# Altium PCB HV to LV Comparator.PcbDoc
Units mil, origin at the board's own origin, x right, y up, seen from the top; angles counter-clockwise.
Board outline 2000 x 2000 mil, 2 copper layers (Top Layer, Bottom Layer), stack 62 mil thick; 42 components, 18 nets, 76 pads, 8 vias.
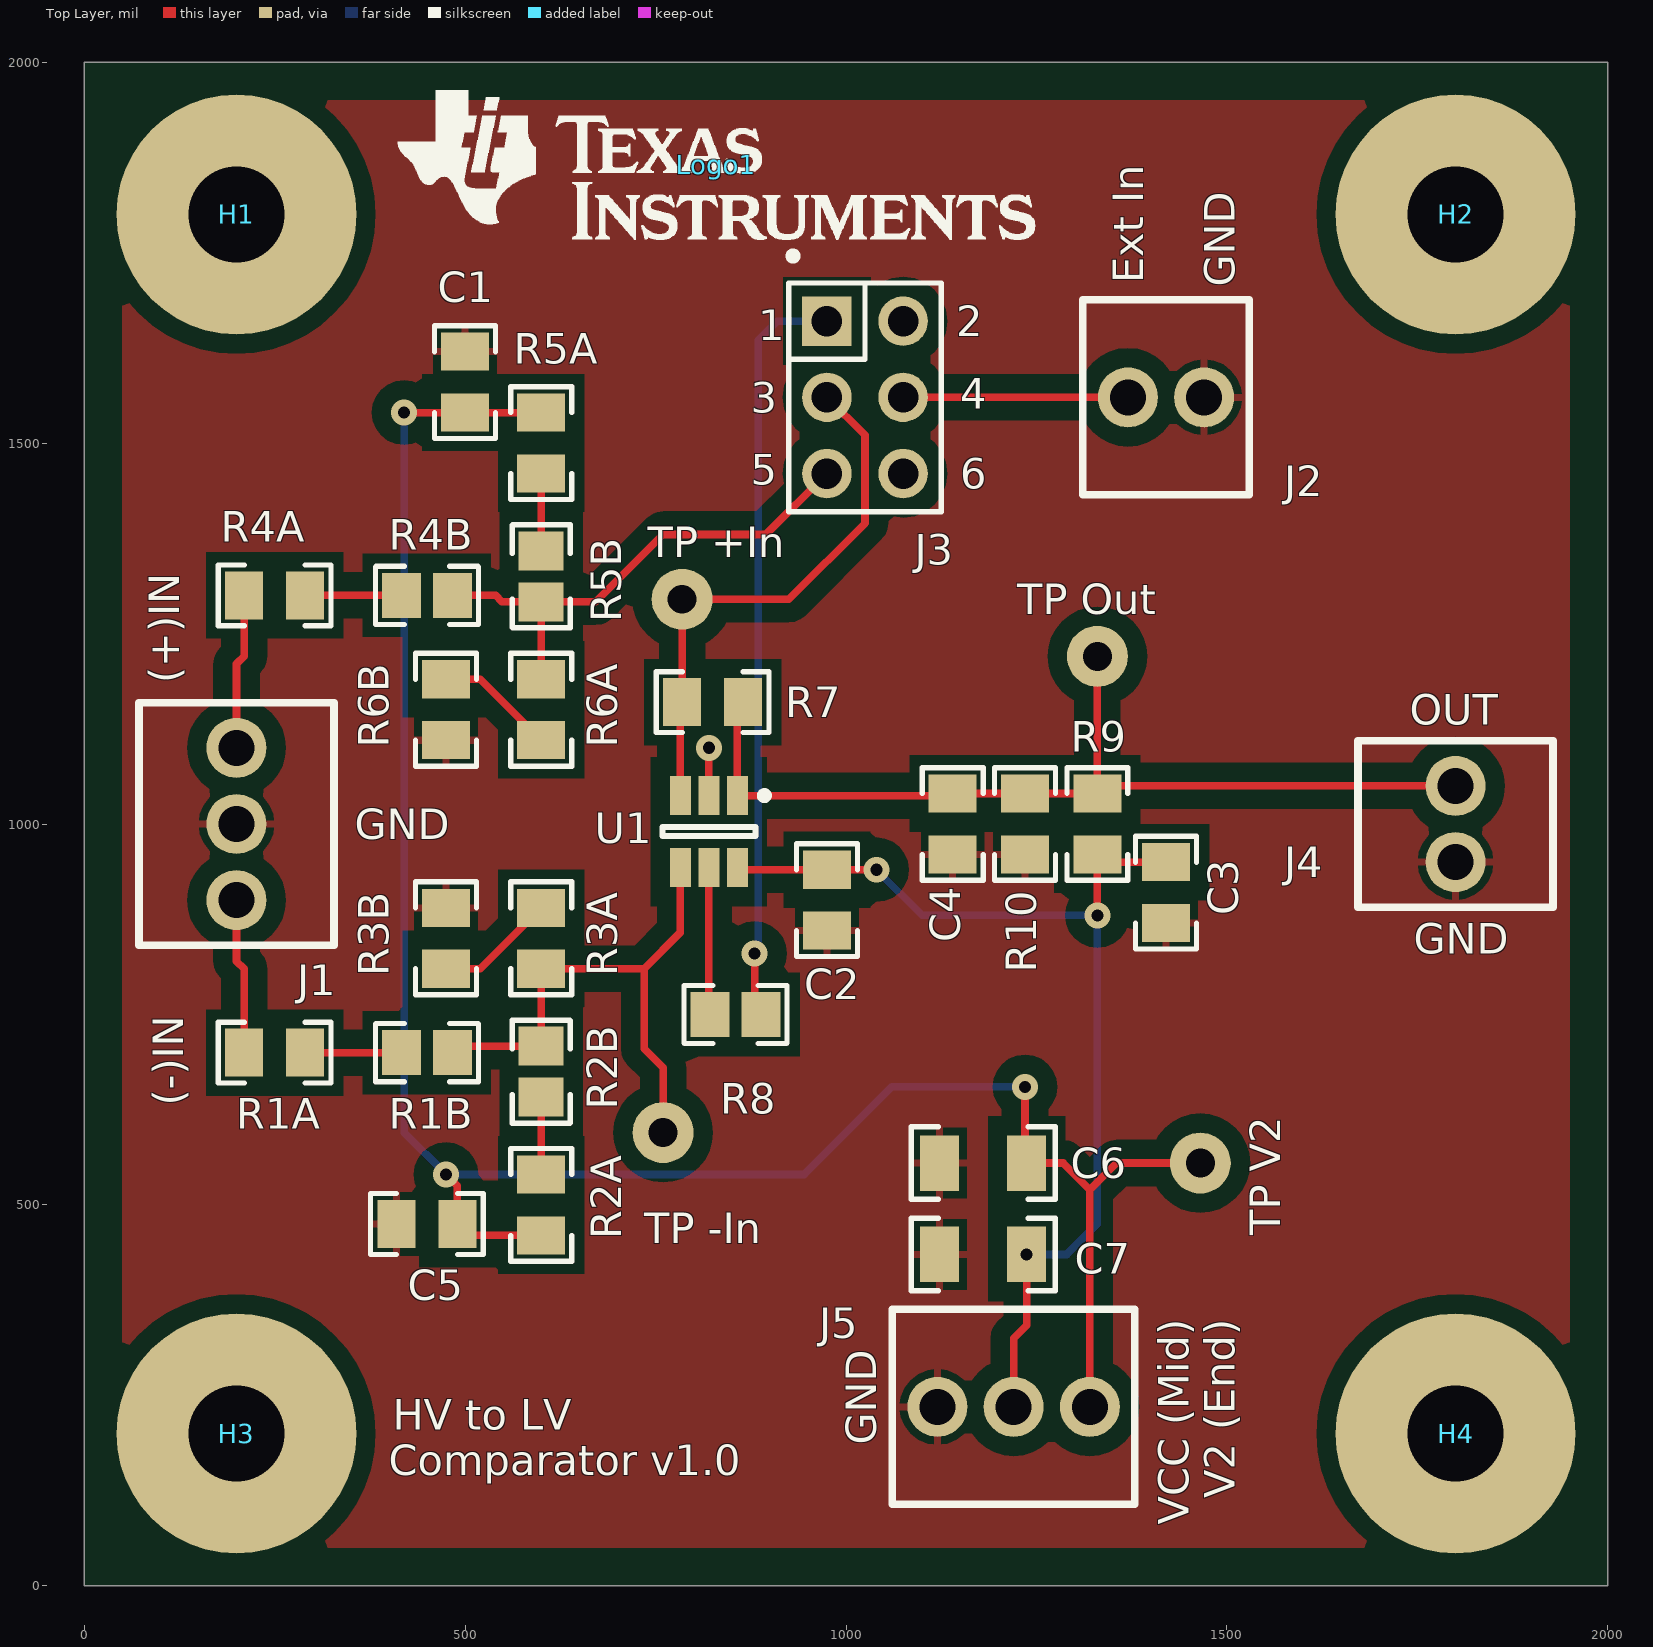
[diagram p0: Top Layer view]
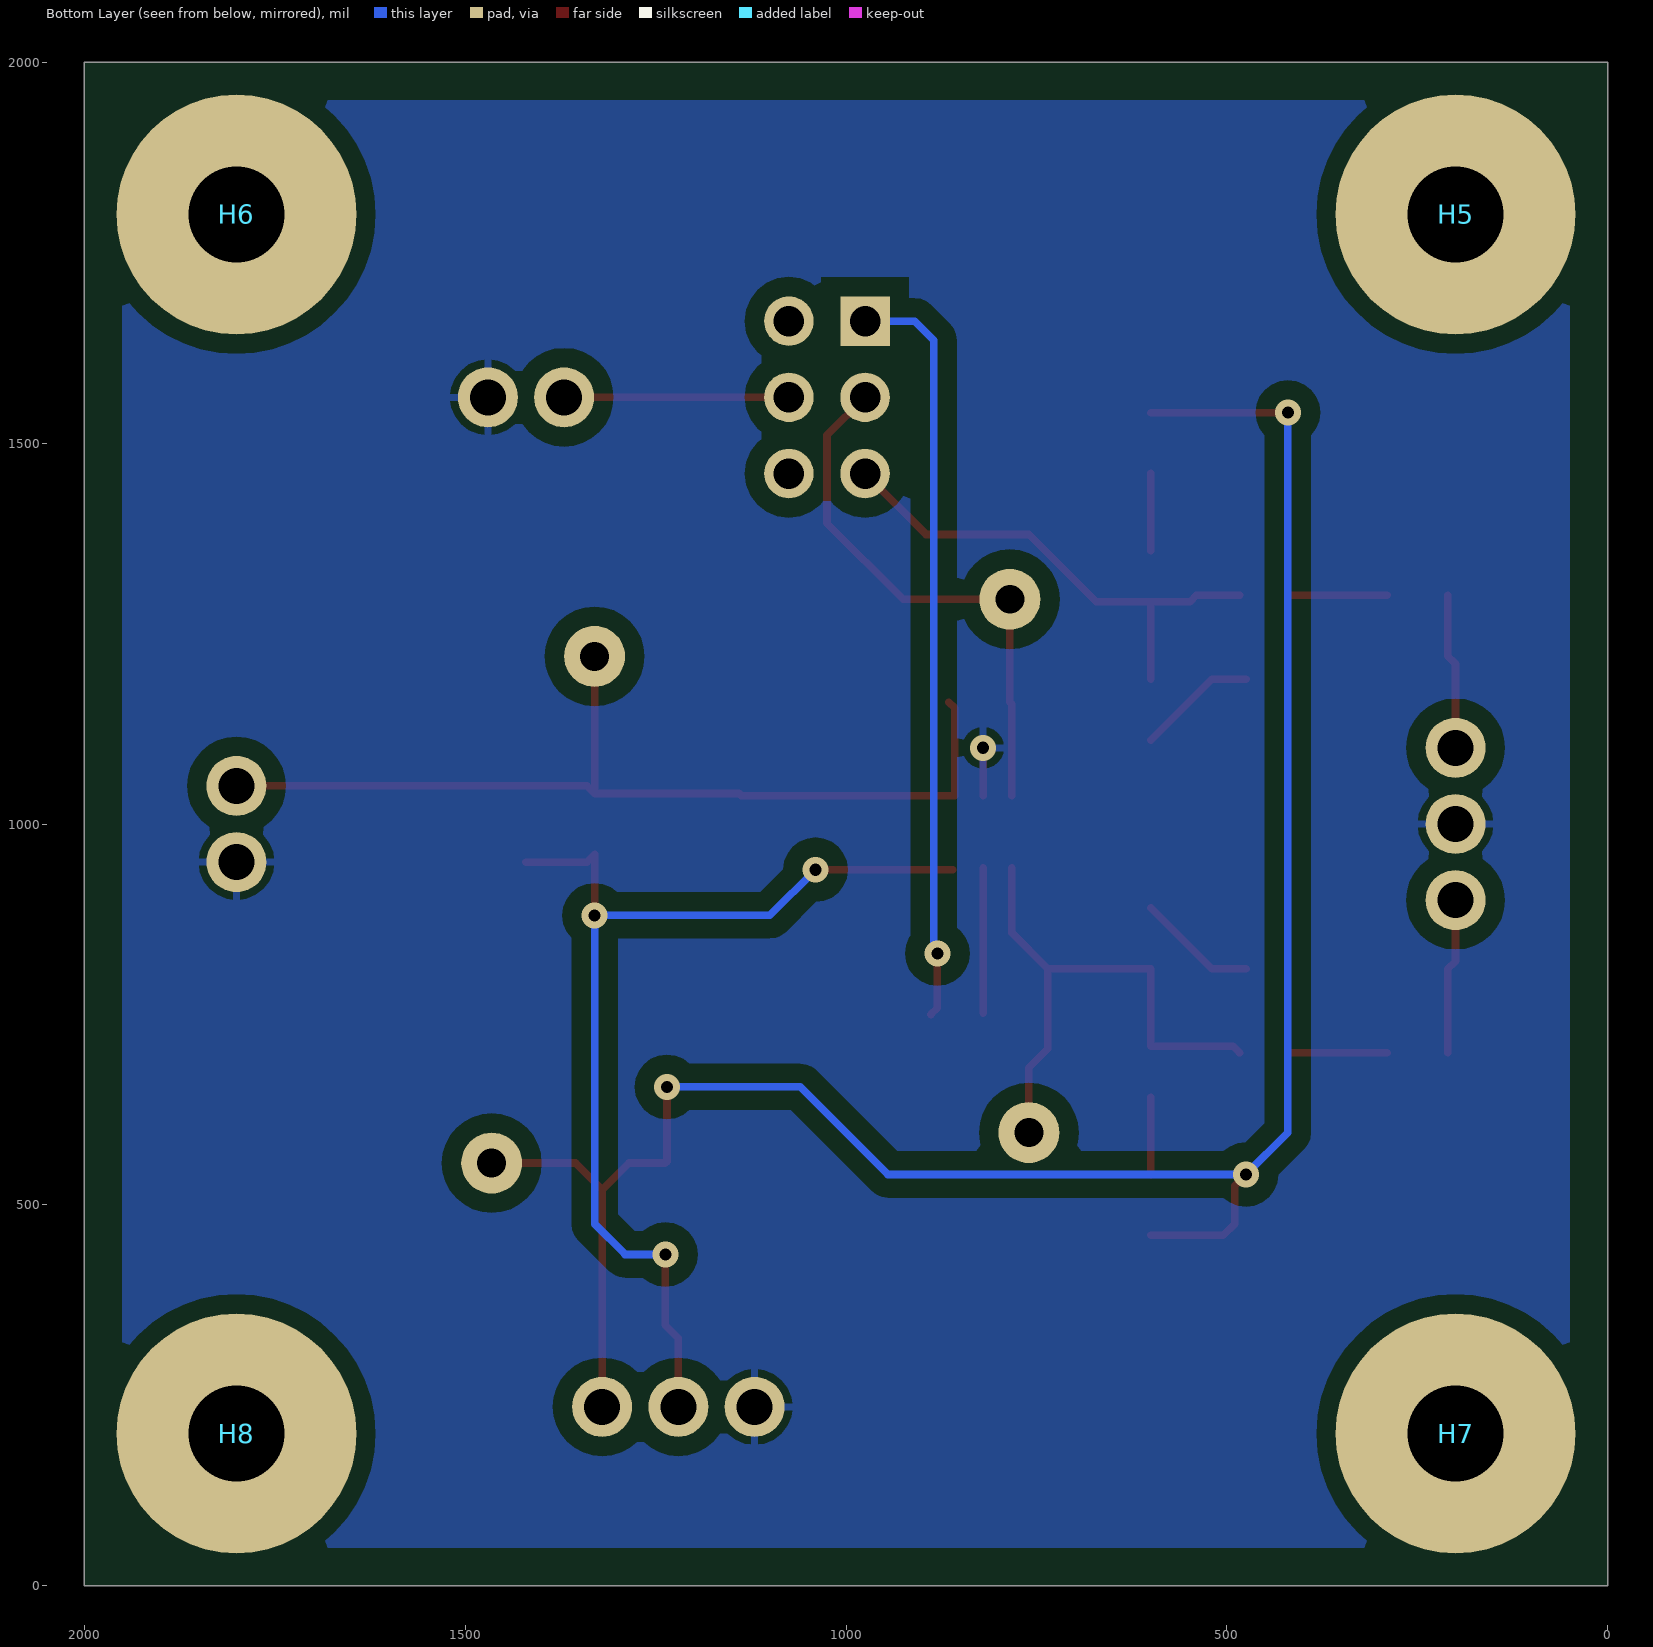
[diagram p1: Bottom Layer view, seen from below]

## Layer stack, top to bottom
Top Layer: signal copper 1.4
Dielectric: core 59.2, FR-4, Dk 4.8
Bottom Layer: signal copper 1.4

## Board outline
0,0 2000,0 2000,2000 0,2000

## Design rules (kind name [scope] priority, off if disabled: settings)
AcuteAngle [All] p1: minimum=4.50000000000000E+0001 checktracksonly=FALSE
AssemblyTestPointUsage [All] p1: valid=2
Clearance Clearance_BoardEdge_MountingHoles [OnCopper and InComponentClass('Mounting Holes') vs IsKeepOut] p1: gap=40
Clearance Clearance_BoardEdge_Poly [OnCopper and InPoly vs IsKeepOut] p2: gap=25
Clearance Clearance_BoardEdge [OnCopper and Not InComponentClass('Logo') and not InComponentClass('FiducialMark') and not InRegion(1000,500,4000,800) and Not IsKeepout vs IsKeepOut] p3: gap=75
Clearance Clearance_Poly [InPolygon] p4: gap=25
Clearance [All] p5: gap=8
ComponentClearance ComponentClearance_Logo [InComponentClass('Logo')] p1: gap=10 collisioncheckmode=3 verticalgap=10 showdistances=FALSE
ComponentClearance ComponentClearance_ScrewToNut [(HasFootprint('NY PMS 440 0025 PH')) vs (HasFootprint('Keystone_1902C'))] p2: gap=5 collisioncheckmode=3 verticalgap=10 showdistances=FALSE
ComponentClearance ComponentClearance_MountingHoles [InComponentClass('Mounting Holes')] p3: gap=50 collisioncheckmode=3 verticalgap=100000 showdistances=FALSE
ComponentClearance ComponentClearance_SmallPassives [HasFootprint('0201*') or HasFootprint('0402*') or HasFootprint('0508') or HasFootprint('0603*') or HasFootprint('0612') or HasFootprint('0805*') or HasFootprint('0815*') or HasFootprint('0830*') or HasFootprint('1206*') or HasFootprint('1210*') or HasFootprint('1808*') or HasFootprint('1812*') or HasFootprint('1825*') or HasFootprint('2010*') or HasFootprint('2220*') or HasFootprint('2225*') or HasFootprint('2512*') or HasFootprint('2728*') or HasFootprint('3518*') vs HasFootprint('0201*') or HasFootprint('0402*') or HasFootprint('0508') or HasFootprint('0603*') or HasFootprint('0612') or HasFootprint('0805*') or HasFootprint('0815*') or HasFootprint('0830*') or HasFootprint('1206*') or HasFootprint('1210*') or HasFootprint('1808*') or HasFootprint('1812*') or HasFootprint('1825*') or HasFootprint('2010*') or HasFootprint('2220*') or HasFootprint('2225*') or HasFootprint('2512*') or HasFootprint('2728*') or HasFootprint('3518*')] p4: gap=20 collisioncheckmode=3 verticalgap=10 showdistances=FALSE
ComponentClearance ComponentClearance_THtoSMT [IsThruComponent vs IsSMTComponent] p5: gap=20 collisioncheckmode=3 verticalgap=10 showdistances=FALSE
ComponentClearance ComponentClearance_THtoTH [IsThruComponent vs IsThruComponent] p6: gap=118.11 collisioncheckmode=3 verticalgap=30 showdistances=FALSE
ComponentClearance [All] p7: gap=40 collisioncheckmode=3 verticalgap=10 showdistances=FALSE
DiffPairsRouting [All] p1: maxlimit=100 minlimit=10 mostfreqgap=10 maxuncoupledlength=1000
FabricationTestPointUsage TestPointUsage [All] p1: valid=2 allowmultiple=FALSE
FabricationTestpoint Testpoint [All] p1: side=3 testpointundercomponent=TRUE minsize=40 maxsize=100 preferedsize=60 minholesize=0 maxholesize=40 preferedholesize=32 testpointgrid=1 allowsidetop=TRUE allowsidebottom=TRUE usegrid=TRUE gridtolerance=0.01
FanoutControl Fanout_LCC [IsLCC] p1: bgadir=Out bgaviamode=Centered fanoutstyle=Auto fanoutdirection=Alternating viagrid=1 // Fanout_LCC (Default Rule)
FanoutControl Fanout_BGA [IsBGA] p2: bgadir=Out bgaviamode=Centered fanoutstyle=Auto fanoutdirection=Alternating viagrid=1 // Fanout_BGA (Default Rule)
FanoutControl Fanout_Default [All] p4: bgadir=Out bgaviamode=Centered fanoutstyle=Auto fanoutdirection=Alternating viagrid=1 // Fanout_Default (Default Rule)
FanoutControl Fanout_Small [(CompPinCount < 5)] p5: bgadir=Out bgaviamode=Centered fanoutstyle=Auto fanoutdirection=OutThenIn viagrid=1 // Fanout_Small (Default Rule)
HoleSize [All] p1: absolutevalues=TRUE maxlimit=251 minlimit=8 maxpercent=80.000 minpercent=20.000
MinimumAnnularRing [All] p1: minimumring=9
MinimumSolderMaskSliver MinimumSolderMaskSliver_Logo [InComponentClass('Logo') vs InComponentClass('Logo')] p1: minsoldermaskwidth=0.7
MinimumSolderMaskSliver [All] p2: minsoldermaskwidth=4
PlaneConnect [All] p1: planeconnectstyle=Relief reliefexpansion=10 reliefentries=4 reliefconductorwidth=10 reliefairgap=10
PolygonConnect [All] p1: connectstyle=Relief reliefconductorwidth=10 reliefentries=4 polygonreliefangle="90 Angle" airgapwidth=10
RoutingVias [All] p1: holewidth=16 width=34 viastyle="Through Hole" minholewidth=8 minwidth=26 maxholewidth=40 maxwidth=65
SMDToCorner [All] p1: distance=30000
SilkToSilkClearance [All] p1: silktosilkclearance=5
SilkscreenOverComponentPads [All] p1: minsilkscreentomaskgap=5
SolderMaskExpansion [All] p1: expansion=3
Width [All] p1: maxlimit=100 minlimit=6 preferedwidth=10 checkconnectedcopper=TRUE
14 further rules are at their usual default settings.

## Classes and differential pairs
component class "Mounting Holes": H1 H2 H3 H4
component class Logo: Logo1
component class Hardware_ANSI-B: H1 H2 H3 H4 H5 H6 H7 H8 Logo1
component class Header: J3
component class HV_LV_Schematic: C1 C2 C3 C4 C5 C6 C7 J1 J2 J3 J4 J5 R1A R1B R2A R2B R3A R3B R4A R4B R5A R5B R6A R6B R7 R8 R9 R10 "TP +In" "TP -In" "TP Out" "TP V2" U1

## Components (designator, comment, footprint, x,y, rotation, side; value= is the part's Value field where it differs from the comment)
C1 "C2012X7R2A103K" 0805_HV 500,1580 r270 top
C2 "C2012X7R2A103K" 0805_HV 975,900 r90 top
C3 "C2012X7R2A103K" 0805_HV 1420,910 r90 top
C4 "C0805C100J1GACTU" 0805_HV 1140,1000 r270 top
C5 "C2012X7R2A103K" 0805_HV 450,475 r180 top
C6 "12063C105KAT2A" 1206 1180,555 r180 top
C7 "12063C105KAT2A" 1206 1180,435 r180 top
H1 "NY PMS 440 0025 PH" "NY PMS 440 0025 PH" 200,1800 r0 top locked
H2 "NY PMS 440 0025 PH" "NY PMS 440 0025 PH" 1800,1800 r0 top locked
H3 "NY PMS 440 0025 PH" "NY PMS 440 0025 PH" 200,200 r0 top locked
H4 "NY PMS 440 0025 PH" "NY PMS 440 0025 PH" 1800,200 r0 top locked
H5 "1902C" Keystone_1902C 200,1800 r180 bottom locked
H6 "1902C" Keystone_1902C 1800,1800 r180 bottom locked
H7 "1902C" Keystone_1902C 200,200 r180 bottom locked
H8 "1902C" Keystone_1902C 1800,200 r180 bottom locked
J1 "282834-3" "3 Contact Terminal Block" 200,900 r90 top
J2 "282834-2" "2 Contact Terminal Block" 1470,1560 r180 top
J3 "TSW-103-07-G-D" TSW-103-07-G-D 1025,1560 r270 top
J4 "282834-2" "2 Contact Terminal Block" 1800,950 r90 top
J5 "282834-3" "3 Contact Terminal Block" 1120,235 r0 top
Logo1 "Texas Instruments" TI_Stacked_Overlay_Small 830,1865 r0 top
R1A "RT0805BRD07232KL" 0805_HV 250,700 r0 top
R1B "Used in BOM report" 0805 450,700 r0 top
R2A "RT0805BRD0749K9L" 0805_HV 600,500 r270 top
R2B "Used in BOM report" 0805 600,675 r270 top
R3A "RT0805BRD0734K4L" 0805_HV 600,850 r270 top
R3B "RT0805BRD07100RL" 0805_HV 475,850 r270 top
R4A "RT0805BRD07232KL" 0805_HV 250,1300 r0 top
R4B "Used in BOM report" 0805 450,1300 r0 top
R5A "RT0805BRD0749K9L" 0805_HV 600,1500 r90 top
R5B "Used in BOM report" 0805 600,1325 r90 top
R6A "RT0805BRD0734K4L" 0805_HV 600,1150 r90 top
R6B "RT0805BRD07100RL" 0805_HV 475,1150 r90 top
R7 "CRCW08051M00FKEA" 0805_HV 825,1160 r0 top
R8 "Used in BOM report" 0805 855,750 r180 top
R9 "CRCW0805100KJNEA" 0805_HV 1330,1000 r270 top
R10 "CRCW0805100KJNEA" 0805_HV 1235,1000 r90 top
"TP +In" "TESTPOINT" TESTPOINT 785,1295 r90 top
"TP -In" "TESTPOINT" TESTPOINT 760,595 r90 top
"TP Out" "TESTPOINT" TESTPOINT 1330,1220 r90 top
"TP V2" "TESTPOINT" TESTPOINT 1465,555 r180 top
U1 "TLV3011AIDBVR" DBV0006A_M 820,990 r270 top

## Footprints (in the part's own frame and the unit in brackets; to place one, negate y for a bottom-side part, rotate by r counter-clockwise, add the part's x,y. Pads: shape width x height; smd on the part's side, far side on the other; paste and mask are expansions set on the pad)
"2 Contact Terminal Block" [mm]
  round 2 hole 1.2: 1(0,0) 2(2.54,0)
  silkscreen extent -1.5,-3.25 4.04,3.25
"3 Contact Terminal Block" [mm]
  round 2 hole 1.2: 1(0,0) 2(2.54,0) 3(5.08,0)
  silkscreen extent -1.5,-3.25 6.58,3.25
0805 [mm] "0805 from SM-752 data"
  rect 1.3x1.5 smd: 1(-0.85,0) 2(0.85,0)
  silkscreen extent -1.72,-0.97 1.72,0.97, body extent -1.1,-0.72 1.1,0.72, height 1.1
0805_HV [mil] "0805 with 30mil clearance between pads"
  rect 50x63 smd: 1(-40,0) 2(40,0)
  silkscreen extent -74,-40 74,40, body extent -43,-29 43,29, height 43
1206 [mm] "1206 from SM-752 data"
  rect 1.3x1.85 smd: 1(-1.45,0) 2(1.45,0)
  silkscreen extent -2.4,-1.21 2.4,1.21, body extent -1.7,-0.9 1.7,0.9, height 1.35
DBV0006A_M [mm] "SOT23, 6-Leads, Body 2.9x1.6mm, Pitch 0.95mm, Lead Span 2.8mm, IPC Low Density"
  rect 1.3x0.7 smd: 1(-1.2,0.95) 2(-1.2,0) 3(-1.2,-0.95) 4(1.2,-0.95) 5(1.2,0) 6(1.2,0.95)
  silkscreen extent -1.32,-1.55 0.15,1.98, body extent -0.87,-1.52 0.87,1.53, height 1.45
Keystone_1902C [mil] "Hex Standoff, 4-40 threaded, nylon"
  body extent -145,-126 146,126, height 501
"NY PMS 440 0025 PH" [mm] "4-40 nylon screw and mounting hole"
  round 8 hole 3.2: 1(0,0)
  body extent -3.3,-3.3 3.3,3.3, height 2.69
TESTPOINT [mil]
  round 80 hole 37.99: 1(0,0)
TI_Stacked_Overlay_Small [mil]
  silkscreen extent -418,-98 418,98
TSW-103-07-G-D [mm] "Samtec 100mil, 2x3, 230 mil above insulator"
  rect 1.65x1.65 hole 1.016 mask+0: 1(-2.54,-1.27)
  round 1.65 hole 1.016 mask+0: 2(-2.54,1.27) 3(0,-1.27) 4(0,1.27) 5(2.54,-1.27) 6(2.54,1.27)
  silkscreen extent -4.83,-2.54 3.81,2.54, body extent -3.81,-2.54 3.81,2.54, height 8.38

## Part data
C1 C2 C3 C5: "CAP, CERM, 0.01uF, 100V, +/-10%, X7R, 0805"
C4: "CAP, CERM, 10pF, 100V, +/-5%, C0G/NP0, 0805"
C6 C7: "CAP, CERM, 1uF, 25V, +/-10%, X7R, 1206"
H1 H2 H3 H4: "Machine Screw, Round, #4-40 x 1/4, Nylon, Philips panhead"
H5 H6 H7 H8: "Standoff, Hex, 0.5\"L #4-40 Nylon"
J1 J5: library part "TERM BLOCK 3POS SIDE ENT", "3 contact eurostyle terminal block"
J2 J4: library part "TERM BLOCK 2POS SIDE ENT", "2 contact eurostyle terminal block"
J3: "Header, TH, 100mil, 3x2, Gold plated, 230 mil above insulator"
Logo1: library part TI_Logo, "Texas Instrument Corporate Signature"
R1A R4A: "RES, 232k ohm, 0.1%, 0.125W, 0805"
R1B R2B R4B R5B R8: library part Resistor, "RES 0.0 OHM 1/8W JUMP 0805 SMD"
R2A R5A: "RES, 49.9k ohm, 0.1%, 0.125W, 0805"
R3A R6A: "RES, 34.4k ohm, 0.1%, 0.125W, 0805"
R3B R6B: "RES, 100 ohm, 0.1%, 0.125W, 0805"
R7: "RES, 1.00Meg ohm, 1%, 0.125W, 0805"
R9 R10: "RES, 100k ohm, 5%, 0.125W, 0805"
"TP +In" "TP -In" "TP Out" "TP V2": "TEST POINT.  No entry in BOM."
U1: "Nanopower, 1.8V, SOT23 Comparator with Voltage Reference"

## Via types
v1: diameter 34, hole 16, Top Layer to Bottom Layer, 8 vias

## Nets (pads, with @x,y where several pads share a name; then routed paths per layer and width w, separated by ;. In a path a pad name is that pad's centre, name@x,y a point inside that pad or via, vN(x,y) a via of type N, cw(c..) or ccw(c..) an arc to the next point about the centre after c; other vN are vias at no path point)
GND: C1.1 C2.1 C3.1 C4.2 C5.2 C6.2 C7.2 J1.2 J2.1 J4.1 J5.1 R3B.1 R6B.1 R10.1 U1.2 | length 62.8
  Top Layer w10: U1.2 v1(820,1100)
NetC4_1: "TP Out.1" C4.1 J4.2 R7.2 R9.1 R10.2 U1.1 | length 1253.8
  Top Layer w10: R7.2 857.4,1152.4 U1.1 1137.24,1037.24 C4.1 R10.2 R9.1 ; 1330,1220 R9.1 ; J4.2 1340,1050 R9.1
NetJ1_1: J1.1 R1A.1 | length 204.1
  Top Layer w10: J1.1 200,820 210,810 R1A.1
NetJ1_3: J1.3 R4A.1 | length 204.1
  Top Layer w10: J1.3 200,1210 210,1220 R4A.1
NetJ2_2: J2.2 J3.4 | length 295
  Top Layer w10: J3.4 J2.2
NetJ3_1: J3.1 R8.1 | length 993.9
  Top Layer w10: v1(880,830) 880,758.46 R8.1
  Bottom Layer w10: v1(880,830) 885,830 885,1635 910,1660 J3.1
NetJ3_3: "TP +In.1" J3.3 R7.1 U1.3 | length 722.5
  Top Layer w10: U1.3 R7.1@782.6,1157.6 ; R7.1 785,1295 925,1295 1025,1395 1025,1510 J3.3
NetJ3_5: J3.5 R4B.2 R5B.1 R6A.2 | length 666.4
  Top Layer w10: R4B.2 540,1300 548.46,1291.54 R5B.1 ; R6A.2 R5B.1 ; J3.5 895,1380 760,1380 671.54,1291.54 R5B.1
NetR1A_2: R1A.2 R1B.1 | length 126.5
  Top Layer w10: R1A.2 R1B.1
NetR1B_2: "TP -In.1" R1B.2 R2B.1 R3A.2 U1.4 | length 734.4
  Top Layer w10: R1B.2 491.93,708.46 R2B.1 R3A.2 735,810 ; 760,595 760,680 735,705 735,810 ; U1.4 782.6,857.6 735,810
NetR2A_1: R2A.1 R2B.2 | length 101.5
  Top Layer w10: R2A.1 R2B.2
NetR3A_1: R3A.1 R3B.2 | length 158.1
  Top Layer w10: R3B.2 520,810 R3A.1
NetR4A_2: R4A.2 R4B.1 | length 126.5
  Top Layer w10: R4A.2 R4B.1
NetR5A_1: R5A.1 R5B.2 | length 101.5
  Top Layer w10: R5B.2 R5A.1
NetR6A_1: R6A.1 R6B.2 | length 158.1
  Top Layer w10: R6B.2 520,1190 R6A.1
NetR8_2: R8.2 U1.5 | length 191.2
  Top Layer w10: R8.2@820,751.54 U1.5
V2: "TP V2.1" C1.2 C5.1 C6.1 J5.3 R2A.2 R5A.2 | length 2837.7
  Top Layer w10: v1(420,1540) C1.2 R5A.2 ; v1(475,540) 490,525 C5.1 505,460 R2A.2 ; C6.1@1235,557.09 v1(1235,655) ; C6.1 1285,555 1320,520 ; J5.3 1320,520 ; 1465,555 1355,555 1320,520
  Bottom Layer w10: v1(420,1540) 420,595 v1(475,540) 945,540 1060,655 v1(1235,655)
VCC: C2.2 C3.2 C7.1 J5.2 R9.2 U1.6 | length 1390.4
  Top Layer w10: U1.6@860.16,940 C2.2 v1(1040,940) ; J5.2 1220,325 1237.09,342.09 v1(1237.09,435) ; v1(1330,880) R9.2 1340,950 C3.2
  Bottom Layer w10: v1(1040,940) 1100,880 v1(1330,880) 1330,475 1290,435 v1(1237.09,435)
pads on no net: H1.1 H2.1 H3.1 H4.1 J3.2 J3.6

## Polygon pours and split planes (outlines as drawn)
GND on Bottom Layer "Bottom Layer-GND" (solid, remove dead copper, pour order 4): 50,1950 50,50 1950,50 1950,1950
GND on Top Layer "Top Layer-GND" (solid, remove dead copper, pour order 2): 50,50 1950,50 1950,1950 50,1950

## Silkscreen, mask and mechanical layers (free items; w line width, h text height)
Top Overlay:
  text "Ext In" at 1390,1710 h40 r90
  text "GND" at 1510,1705 h40 r90
  text "2" at 1145,1640 h40
  text "1" at 885,1635 h40
  text "4" at 1150,1545 h40
  text "3" at 875,1540 h40
  text "5" at 875,1445 h40
  text "6" at 1150,1440 h40
  text "(+)IN" at 125,1185 h40 r90
  text "OUT" at 1740,1130 h40
  text "GND" at 355,980 h40
  text "GND" at 1745,830 h40
  text "(-)IN" at 130,630 h40 r90
  text "HV to LV" at 405,205 h40
  text "GND" at 1040,185 h40 r90
  text "Comparator v1.0" at 400,145 h40
  text "V2 (End)" at 1510,115 h40 r90
  text "VCC (Mid)" at 1450,80 h40 r90
M1 Board Outline:
  the board outline again, w10
M2 Board Dimensions:
  rectangle: -0.5,-285.5 124.5,-160.5
  rectangle: 124.5,-410.5 499.5,-285.5
  lines w7: -0.5,-285.5 999.5,-285.5 ; 124.5,-410.5 124.5,-160.5 ; 249.5,-410.5 249.5,-160.5 ; 499.5,-410.5 499.5,-160.5 ; 749.5,-410.5 749.5,-160.5 ; -0.5,-410.5 999.5,-410.5 999.5,-160.5 -0.5,-160.5 -0.5,-410.5
  lines w10: -0.5,-475.5 -0.5,-455.5 ; 59.5,-485.5 -0.5,-465.5 ; 59.5,-445.5 -0.5,-465.5 ; 223.58,-465.5 -0.5,-465.5 ; 775.42,-465.5 999.5,-465.5 ; 939.5,-485.5 999.5,-465.5 ; 939.5,-445.5 999.5,-465.5 ; 999.5,-475.5 999.5,-455.5
  text "1000 (mil)" at 233.58,-501.49 h60
  text ".Layer_Name" at 577,-858.49 h60
M3 3D STEP Top:
  text ".Layer_Name" at 577,-858.49 h60
M4 3D STEP Bottom:
  text ".Layer_Name" at 577,-858.49 h60
M5 Assembly Top:
  lines w7: 5139,110.5 6264,110.5 ; 5139,233 6261.5,233 ; 5454,-9.5 5454,353 ; 5839,-9.5 5139,-9.5 ; 5839,353 5139,353 ; 5139,-9.5 6264,-9.5 6264,353 5139,353 ; 5139,-9.5 5139,353
  lines w10: -292,-930.17 6308,-930.17 ; -292,-726.83 6310,-726.83 ; -292,-523.5 -292,-1133.5 3713,-1133.5 6310,-1133.5 6310,-523.5 -291.5,-523.5 -291.5,-1133.5 1284,-1133.5 ; 2173,-1133.5 2173,-523.5 ; 3440,-726.83 3440,-523.5 ; 4280,-726.83 4280,-523.5 ; 4902,-1140 4902,-937.17
  text "TABLE 1" at 5526.5,388 h40
  text "Variant" at 5164,278 h40
  text "Label text" at 5599,278 h40
  text "001" at 5231.5,158 h40
  text "ChangeMe!" at 5509,155.5 h40
  text "002" at 5231.5,33 h40
  text "ChangeMe!" at 5504,30.5 h40
  text "COMPONENTS MARKED 'DNP' SHOULD NOT BE POPULATED." at 1153.5,-318.5 h60
  text "ASSEMBLY VARIANT:" at 1153,-434 h60
  text ".VariantName" at 2189,-434 h60
  text "PCB VIEWED FROM TOP SIDE" at -228.5,-655.67 h60
  text "BOARD #:" at 2248,-655.67 h60
  text ".PRJ_Number" at 2793.5,-655.67 h60
  text "REV:" at 3638,-655.67 h60
  text ".PCB_Rev" at 3929.5,-655.67 h60
  text "SVN REV:" at 4476,-655.67 h60
  text ".VersionControl_RevNumber" at 4982,-655.67 h60
  text "IGNORE ->" at -228.5,-858.49 h60
  text "PLOT NAME =" at -228.5,-1064.34 h60
  text ".plot_File_Name" at 577,-1064.34 h60
  text "GENERATED    :" at 2250,-1064.34 h60
  text ".Print_Date" at 3119.5,-1064.34 h60
  text ".Print_Time" at 3848.5,-1064.34 h60
  text "TEXAS INSTRUMENTS" at 5113,-1064.34 h60
M6 Assembly Bottom:
  lines w10: -292.5,-727.33 6309.5,-727.33 ; -290.5,-930.67 6309.5,-930.67 ; 1115.5,-1140.5 1115.5,-937.67 ; 1737.5,-727.33 1737.5,-524 ; 2577.5,-727.33 2577.5,-524 ; 3844.5,-1134 3844.5,-524 ; 4733.5,-1134 6309,-1134 6309,-524 -292.5,-524 -292.5,-1134 2304.5,-1134 6309.5,-1134 6309.5,-524
  text "COMPONENTS MARKED 'DNP' SHOULD NOT BE POPULATED." at 6102,-318 h60
  text ".VariantName" at 5058,-434 h60
  text "ASSEMBLY VARIANT:" at 6097,-434 h60
  text ".VersionControl_RevNumber" at 1035.5,-656.17 h60
  text "SVN REV:" at 1541.5,-656.17 h60
  text ".PCB_Rev" at 2088,-656.17 h60
  text "REV:" at 2379.5,-656.17 h60
  text ".PRJ_Number" at 3224,-656.17 h60
  text "BOARD #:" at 3769.5,-656.17 h60
  text "PCB VIEWED FROM BOTTOM SIDE" at 6246,-656.17 h60
  text "IGNORE ->" at 2547.85,-858.49 h60
  text "TEXAS INSTRUMENTS" at 904.5,-1064.84 h60
  text ".Print_Time" at 2169,-1064.84 h60
  text ".Print_Date" at 2898,-1064.84 h60
  text "GENERATED    :" at 3767.5,-1064.84 h60
  text ".plot_File_Name" at 5440.5,-1064.84 h60
  text "PLOT NAME =" at 6246,-1064.84 h60
M9 Title Sheet:
  drawing of 57 lines, arcs and shapes, not listed
  text "1" at 739.84,8036.5 h70
  text "2" at 3235.5,8036.5 h70
  text "3" at 5724.84,8036.5 h70
  text "4" at 8231.51,8036.5 h70
  text "5" at 10730.5,8036.5 h70
  text "6" at 13235.5,8036.5 h70
  text "A" at -416.5,6893.5 h70
  text "A" at 14383.5,6893.5 h70
  text "B" at -416.5,4513.5 h70
  text "B" at 14383.5,4513.5 h70
  text "C" at -416.5,2138.5 h70
  text "C" at 14383.5,2138.5 h70
  text "PROJECT TITLE:" at 11343.5,277.5 h45
  text ".PRJ_Title" at 11393.5,144.17 h70
  text "DESIGNED FOR:" at 11343.5,-23.5 h45
  text ".PRJ_Customer" at 11393.5,-163.5 h70
  text "D" at -416.5,-231.5 h70
  text "D" at 14383.5,-231.5 h70
  text "FILE NAME:" at 11343.5,-323.5 h45
  text ".PCB_File_Name_No_Path" at 11393.5,-443.5 h70
  text "Texas Instruments (TI) and/or its licensors do not warrant the accuracy or completeness of this specification" at 6374,-605.34 h45
  text "ENGINEER:" at 11343.5,-613.5 h45
  text "LAYOUT BY:" at 12848.5,-613.5 h45
  text "or any information contained therein. TI and/or its licensors do not warrant that this design will meet" at 6329.01,-718 h45
  text ".PRJ_Engineer" at 11393.5,-768.49 h70
  text ".PCB_Layout" at 12899,-768.49 h70
  text "the specifications, will be suitable for your application or fit for any particular purpose, or will operate in" at 6329.01,-830.67 h45
  text ".Layer_Name" at 577,-858.49 h60
  text "ALTIUM DESIGNER VERSION:" at 12848.5,-923.5 h45
  text "an implementation. TI and/or its licensors do not warrant that the design is production worthy. You should" at 6329.01,-943.33 h45
  text "completely validate and test your design implementation to confirm the system functionality for your application." at 6374,-1056 h45
  text ".print_Scale" at 11393.5,-1056.83 h70
  text ".Application_BuildNumber" at 12899,-1056.83 h70
  text "1" at 739.84,-1263.5 h70
  text "2" at 3235.5,-1263.5 h70
  text "3" at 5724.84,-1263.5 h70
  text "4" at 8231.51,-1263.5 h70
  text "5" at 10730.5,-1263.5 h70
  text "6" at 13235.5,-1263.5 h70
M10 Fab Notes:
  drawing of 212 lines, arcs and shapes, not listed
  text "DESIGN INFORMATION" at 12381.02,6810 h60
  text "(REFER ALSO ARRAY/PANEL PROFILING INFORMATION)" at 12019.46,6648.29 h60
  text "BOARD SIZE" at 11333.46,6644 h60
  text "3450MIL" at 11795.78,6516.18 h60
  text "X" at 12301.46,6516.18 h60
  text "4950MIL" at 12532.78,6516.18 h60
  text "Number of Layers :" at 11736.46,6319 h60
  text "2" at 12831.27,6309 h60
  text "MIN. TRACK WIDTH:" at 11736.46,6180 h60
  text "8" at 12832.7,6180 h60
  text "MIL" at 12987.46,6180 h60
  text "MIN. CLEARANCE:" at 11736.46,6048 h60
  text "8" at 12832.7,6048 h60
  text "MIL" at 12987.46,6048 h60
  text "MIN. VIA PAD SIZE:" at 11736.46,5916 h60
  text "24" at 12802.71,5916 h60
  text "MIL" at 12987.46,5916 h60
  text "0.05mm (2MIL)" at 12431.46,5774.29 h60
  text "MINIMUM ANNULAR RING" at 11407.23,5770 h60
  text "EXTERNAL" at 13139.46,5770 h60
  text "PER" at 11607.23,5652 h60
  text "IPC-D-275 CLASS 2 LEVEL C" at 11827.23,5652 h60
  text "MIL, HOLES" at 13315.46,5539.71 h60
  text "+/-" at 12923,5539 h60
  text "+/-" at 13777,5539 h60
  text "REGISTRATION TOLERANCES:" at 11407.23,5534 h60
  text "METAL" at 12607,5534 h60
  text "5" at 13183.2,5534 h60
  text "3" at 14016.2,5534 h60
  text "MIL" at 14132.46,5534 h60
  text "MATERIAL:" at 11332.46,5324.54 h60
  text "FR-4 High Tg" at 12318.9,5184.21 h60
  text "FR-408" at 11753.46,5175.64 h60
  text "X" at 12165.46,5175.64 h60
  text "OTHER" at 13241.46,5175.64 h60
  text "62 MIL (1.6mm) +/-10%" at 12073.56,5012.92 h60
  text "THICKNESS:" at 11407.23,5008.64 h60
  text "X" at 11945.4,5008.64 h60
  text "OTHER" at 13358.46,5008.64 h60
  text "TOLERANCE:" at 11407.23,4850.64 h60
  text "X" at 12246.53,4850.64 h60
  text "ANSI IPC-6012 TYPE 3 CLASS 2" at 12433.48,4850.64 h60
  text "OTHER +/-" at 12433.46,4694.64 h60
  text "BOW & TWIST:" at 11407.23,4537.64 h60
  text "X" at 12246.53,4537.64 h60
  text "ANSI IPC-6012 TYPE 3 CLASS 2" at 12433.48,4537.64 h60
  text "OTHER +/-" at 12433.46,4379.13 h60
  text "COPPER THICKNESS (FINISHED):" at 11332.46,4243.64 h60
  text "1.4MIL (1oz)" at 12212.46,4090.92 h60
  text "2MIL (1.4oz)" at 12979.46,4090.92 h60
  text "2.8MIL (2oz)" at 13706.46,4090.92 h60
  text "OUTER:" at 11689.46,4086.64 h60
  text "X" at 12084,4086 h60
  text "1.4MIL (1oz)" at 12212.46,3933.92 h60
  text "2.8MIL (2oz)" at 12979.46,3933.92 h60
  text "N/A" at 13706,3934.29 h60
  text "INNER SIGNAL:" at 11400.38,3929.64 h60
  text "X" at 12085.42,3929.64 h60
  text "DRILLING:" at 11332.46,3790.64 h60
  text "REFERENCE:" at 11407.23,3673.64 h60
  text "X" at 12055.46,3673.64 h60
  text "AS SHOWN" at 12242.46,3673.64 h60
  text "X" at 12956.46,3673.64 h60
  text "NC_DRILL FILES" at 13093.46,3673.64 h60
  text "PTH MIN COPPER THICKNESS:" at 11407.23,3515.64 h60
  text "X" at 12757.46,3515.64 h60
  text "1MIL" at 12894.46,3515.64 h60
  text "OTHER" at 13391.46,3515.64 h60
  text "BOARD FINISH:" at 11332.46,3356.64 h60
  text "SILKSCREEN:" at 11487.68,3238.64 h60
  text "X" at 12436.46,3238.64 h60
  text "TOP" at 12562.46,3238.64 h60
  text "X" at 12946.46,3238.64 h60
  text "BOTTOM" at 13073.46,3238.64 h60
  text "SILKSCREEN COLOR:" at 11487.68,3071.64 h60
  text "X" at 12435.42,3071.64 h60
  text "WHITE" at 12562.46,3071.64 h60
  text "OTHER" at 13073.46,3071.64 h60
  text "SOLDER RESIST COLOR:" at 11487.68,2901.64 h60
  text "X" at 12055.42,2742.44 h60
  text "GREEN" at 12182.46,2742.44 h60
  text "BLUE" at 12773.46,2742.44 h60
  text "OTHER" at 13311.46,2742.44 h60
  text "IMMERSION GOLD (ENIG)" at 12393.46,2553.92 h60
  text "ENEPIG" at 13731,2550.64 h60
  text "SURFACE FINISH:" at 11332.46,2549.64 h60
  text "X" at 12206.51,2549.64 h60
  text "IMM. TIN/SILVER OR EQUIV" at 11662,2392.64 h60
  text "OTHER" at 13093.46,2392.64 h60
  text "ARRAY/PANEL:" at 11332.46,2213.64 h60
  text "CUT AND TRIM PER MECH LAYER 1" at 12393.46,2209.35 h60
  text "N.C. ROUTE" at 12393.46,2057.64 h60
  text "X" at 13072.46,2057.64 h60
  text "V. SCORE" at 13259.46,2057.64 h60
  text "CERTIFICATION:" at 11332.46,1920.64 h60
  text "MATERIALS AND WORKMANSHIP FOR ALL PCBS" at 12057.46,1920.64 h60
  text "TO MEET OR EXCEED THE REQUIREMENTS OF:" at 12057.46,1822.64 h60
  text "X" at 11683.96,1686.13 h60
  text "ANSI IPC-A-600F CLASS ->" at 11822.96,1686.13 h60
  text "X" at 13462.02,1686.13 h60
  text "2" at 13580.96,1686.14 h60
  text "1" at 13265.96,1684.64 h60
  text "3" at 13934.96,1684.64 h60
  text "X" at 11686.02,1526.64 h60
  text "UL 94V-0" at 11822.96,1526.64 h60
  text "X" at 12498.02,1526.64 h60
  text "RoHS" at 12634.96,1526.64 h60
  text "OTHER" at 13279.36,1526.64 h60
  text "PER ORDER" at 13676.42,1526.64 h60
  text "ADDITIONAL REQUIREMENTS:" at 11332.46,1385.64 h60
  text "MICROSECTION:" at 11407.23,1270.64 h60
  text "YES" at 12312.96,1270.64 h60
  text "REQUIRED" at 13174.46,1114.49 h60
  text "BARE BOARD ELEC. TEST:" at 11407.23,1111.64 h60
  text "NONE" at 12712.96,1111.64 h60
  text "X" at 13047.46,1111.64 h60
  text "PER ORDER" at 13766.46,1111.64 h60
  text "MANUFACTURER'S UL:" at 11407.23,954.64 h60
  text "RAIL" at 12572.96,950.35 h60
  text "METAL" at 13064.77,950.35 h60
  text "X" at 13440,950 h60
  text "SILK" at 13576.46,950.35 h60
  text ".Layer_Name" at 577,-858.49 h60
M11 Gerber Information:
  lines w10: -292,-930.17 6308,-930.17 ; -292,-726.83 6310,-726.83 ; -292,-523.5 -292,-1133.5 3713,-1133.5 6310,-1133.5 6310,-523.5 -291.5,-523.5 -291.5,-1133.5 1284,-1133.5 ; 2173,-1133.5 2173,-523.5 ; 3440,-726.83 3440,-523.5 ; 4280,-726.83 4280,-523.5 ; 4902,-1140 4902,-937.17
  text "ALL ARTWORK VIEWED FROM TOP SIDE" at -228.5,-655.67 h60
  text "BOARD #:" at 2248,-655.67 h60
  text ".PRJ_Number" at 2793.5,-655.67 h60
  text "REV:" at 3638,-655.67 h60
  text ".PCB_Rev" at 3929.5,-655.67 h60
  text "SVN REV:" at 4476,-655.67 h60
  text ".VersionControl_RevNumber" at 4982,-655.67 h60
  text "LAYER NAME =" at -228.5,-858.49 h60
  text "PLOT NAME =" at -228.5,-1064.34 h60
  text ".plot_File_Name" at 577,-1064.34 h60
  text "GENERATED    :" at 2250,-1064.34 h60
  text ".Print_Date" at 3119.5,-1064.34 h60
  text ".Print_Time" at 3848.5,-1064.34 h60
  text "TEXAS INSTRUMENTS" at 5113,-1064.34 h60
M12 Stackup:
  lines w6: 11360,7460 13910,7460 ; 11360,7564.4 13910,7564.4 ; 11300,6975 ccw(c11334,6975) 11334,6941 13936,6941 ccw(c13936,6975) 13970,6975 13970,7681 ccw(c13936,7681) 13936,7715 11334,7715 ccw(c11334,7681) 11300,7681 11300,6975
  text "The Stackup Legend below this is static." at 11605.5,7874.5 h60
  text "If you change the stackup, update the Legend." at 11615.5,7784.5 h60
  text "Layer Stack Up Detail for: Ref_Design.PcbDoc" at 11360,7597.1 h57
  text "Layer" at 11360,7525.4 h24
  text "Gerber" at 12255.81,7525.4 h24
  text "Copper" at 12819.33,7525.4 h24
  text "Dielectric" at 13422.04,7525.4 h24
  text "Name" at 11360,7477.4 h24
  text "Document" at 12255.81,7477.4 h24
  text "Thickness" at 12819.33,7477.4 h24
  text "Material" at 13422.04,7477.4 h24
  text "Top Solder Mask" at 11360,7384.44 h34
  text "(.GTS)" at 12255.81,7384.44 h34
  text "Solder Resist" at 13422.04,7384.44 h34
  text "Top Layer" at 11360,7287.69 h34
  text "(.GTL)" at 12255.81,7287.69 h34
  text "1.4mil" at 12819.33,7287.69 h34
  text "FR-4" at 13422.04,7239.31 h34
  text "Bottom Layer" at 11360,7190.94 h34
  text "(.GBL)" at 12255.81,7190.94 h34
  text "1.4mil" at 12819.33,7190.94 h34
  text "Bottom Solder Mask" at 11360,7094.19 h34
  text "(.GBS)" at 12255.81,7094.19 h34
  text "Solder Resist" at 13422.04,7094.19 h34
  text ".Layer_Name" at 577,-858.49 h60
M13 Component Bodies Top:
  text ".Layer_Name" at 577,-858.49 h60
M14 Component Bodies Bottom:
  text ".Layer_Name" at 577,-858.49 h60
M15 Courtyards Top:
  text ".Layer_Name" at 577,-858.49 h60
M16 Courtyards Bottom:
  text ".Layer_Name" at 577,-858.49 h60

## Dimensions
0,0 to 0,2000 on M2 Board Dimensions
0,0 to 2000,0 on M2 Board Dimensions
